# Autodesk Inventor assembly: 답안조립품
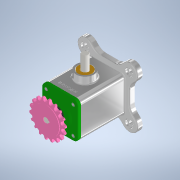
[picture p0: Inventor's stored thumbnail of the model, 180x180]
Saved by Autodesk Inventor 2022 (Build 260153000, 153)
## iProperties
Created: 2022-05
Part Number: 답안조립품
Document SubType Name: Assembly
Designer: Admin
Author: Admin
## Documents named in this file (11)
- C:\Users\Admin\Desktop\720509V1006\답안조립품.iam
- C:\Users\Admin\Desktop\720509V1006\본체.ipt
- C:\Users\Admin\Desktop\720509V1006\커버.ipt
- C:\Users\Admin\Desktop\720509V1006\베어링 6203.ipt
- C:\Users\Admin\Desktop\720509V1006\편심축.ipt
- C:\Users\Admin\Desktop\720509V1006\오일 실.ipt
- C:\Users\Admin\Desktop\720509V1006\부시.ipt
- C:\Users\Admin\Desktop\720509V1006\슬라이더.ipt
- C:\Users\Admin\Desktop\720509V1006\키 4 x 4 x 14.ipt
- C:\Users\Admin\Desktop\720509V1006\스프로킷.ipt
- C:\Users\Admin\Desktop\720509V1006\볼트 M4.ipt
